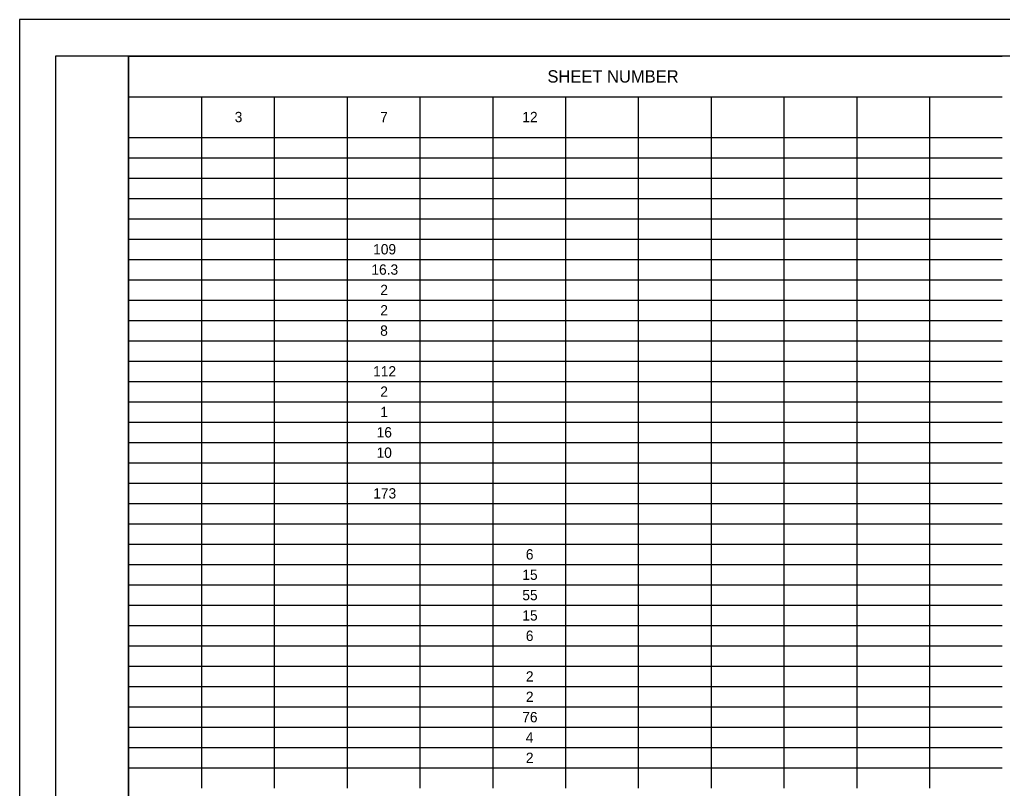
# Model space of a CAD drawing. Extents: x 0 to 34, y 0 to 22.
# Drawn here: x 0 to 13.53, y 11.42 to 22 of the extents above; entities that cross this region are included whole.
import ezdxf

# ---------------------------------------------------------------- set-up
doc = ezdxf.new("R2010")
doc.units = 0
for name, color, linetype in [('Default', 7, 'Continuous'), ('SH_Border', 7, 'Continuous'), ('SH_Cut_Line', 7, 'Continuous')]:
    doc.layers.add(name, color=color, linetype=linetype)

msp = doc.modelspace()

# ---------------------------------------------------------------- linework, layer by layer
at = {"layer": 'Default'}
for p, q in [((1.5, 21.499), (6.513, 21.499)), ((1.5, 21.499), (1.5, 21.219)), ((6.513, 21.499), (7.515, 21.499)), ((7.515, 21.499), (12.528, 21.499)), ((12.528, 21.499), (13.53, 21.499)), ((1.5, 21.219), (1.5, 20.939)), ((1.5, 20.939), (6.513, 20.939)), ((1.5, 20.939), (1.5, 20.659)), ((2.503, 20.939), (2.503, 20.659)), ((3.505, 20.939), (3.505, 20.659)), ((4.508, 20.939), (4.508, 20.659)), ((5.51, 20.939), (5.51, 20.659)), ((6.513, 20.939), (7.515, 20.939)), ((6.513, 20.939), (6.513, 20.659)), ((7.515, 20.939), (12.528, 20.939)), ((7.515, 20.939), (7.515, 20.659)), ((8.518, 20.939), (8.518, 20.659)), ((9.52, 20.939), (9.52, 20.659)), ((10.523, 20.939), (10.523, 20.659)), ((11.525, 20.939), (11.525, 20.659)), ((12.528, 20.939), (13.53, 20.939)), ((12.528, 20.939), (12.528, 20.659)), ((1.5, 20.659), (1.5, 20.379)), ((2.503, 20.659), (2.503, 20.379)), ((3.505, 20.659), (3.505, 20.379)), ((4.508, 20.659), (4.508, 20.379)), ((5.51, 20.659), (5.51, 20.379)), ((6.513, 20.659), (6.513, 20.379)), ((7.515, 20.659), (7.515, 20.379)), ((8.518, 20.659), (8.518, 20.379)), ((9.52, 20.659), (9.52, 20.379)), ((10.523, 20.659), (10.523, 20.379)), ((11.525, 20.659), (11.525, 20.379)), ((12.528, 20.659), (12.528, 20.379)), ((1.5, 20.379), (6.513, 20.379)), ((1.5, 20.379), (1.5, 20.099)), ((2.503, 20.379), (2.503, 20.099)), ((3.505, 20.379), (3.505, 20.099)), ((4.508, 20.379), (4.508, 20.099)), ((5.51, 20.379), (5.51, 20.099)), ((6.513, 20.379), (7.515, 20.379)), ((6.513, 20.379), (6.513, 20.099)), ((7.515, 20.379), (12.528, 20.379)), ((7.515, 20.379), (7.515, 20.099)), ((8.518, 20.379), (8.518, 20.099)), ((9.52, 20.379), (9.52, 20.099)), ((10.523, 20.379), (10.523, 20.099)), ((11.525, 20.379), (11.525, 20.099)), ((12.528, 20.379), (13.53, 20.379)), ((12.528, 20.379), (12.528, 20.099)), ((1.5, 20.099), (6.513, 20.099)), ((1.5, 20.099), (1.5, 18.7)), ((2.503, 20.099), (2.503, 18.7)), ((3.505, 20.099), (3.505, 18.7)), ((4.508, 20.099), (4.508, 18.7)), ((5.51, 20.099), (5.51, 18.7)), ((6.513, 20.099), (7.515, 20.099)), ((6.513, 20.099), (6.513, 18.7)), ((7.515, 20.099), (12.528, 20.099)), ((7.515, 20.099), (7.515, 18.7)), ((8.518, 20.099), (8.518, 18.7)), ((9.52, 20.099), (9.52, 18.7)), ((10.523, 20.099), (10.523, 18.7)), ((11.525, 20.099), (11.525, 18.7)), ((12.528, 20.099), (13.53, 20.099)), ((12.528, 20.099), (12.528, 18.7)), ((1.5, 19.819), (6.513, 19.819)), ((6.513, 19.819), (7.515, 19.819)), ((7.515, 19.819), (12.528, 19.819)), ((12.528, 19.819), (13.53, 19.819)), ((1.5, 19.539), (6.513, 19.539)), ((6.513, 19.539), (7.515, 19.539)), ((7.515, 19.539), (12.528, 19.539)), ((12.528, 19.539), (13.53, 19.539)), ((1.5, 19.259), (6.513, 19.259)), ((6.513, 19.259), (7.515, 19.259)), ((7.515, 19.259), (12.528, 19.259)), ((12.528, 19.259), (13.53, 19.259)), ((1.5, 18.98), (6.513, 18.98)), ((6.513, 18.98), (7.515, 18.98)), ((7.515, 18.98), (12.528, 18.98)), ((12.528, 18.98), (13.53, 18.98)), ((1.5, 18.7), (6.513, 18.7)), ((1.5, 18.7), (1.5, 18.14)), ((2.503, 18.7), (2.503, 18.14)), ((3.505, 18.7), (3.505, 18.14)), ((4.508, 18.7), (4.508, 18.14)), ((5.51, 18.7), (5.51, 18.14)), ((6.513, 18.7), (7.515, 18.7)), ((6.513, 18.7), (6.513, 18.14)), ((7.515, 18.7), (12.528, 18.7)), ((7.515, 18.7), (7.515, 18.14)), ((8.518, 18.7), (8.518, 18.14)), ((9.52, 18.7), (9.52, 18.14)), ((10.523, 18.7), (10.523, 18.14)), ((11.525, 18.7), (11.525, 18.14)), ((12.528, 18.7), (13.53, 18.7)), ((12.528, 18.7), (12.528, 18.14)), ((1.5, 18.42), (6.513, 18.42)), ((6.513, 18.42), (7.515, 18.42)), ((7.515, 18.42), (12.528, 18.42)), ((12.528, 18.42), (13.53, 18.42)), ((1.5, 18.14), (6.513, 18.14)), ((1.5, 18.14), (1.5, 17.86)), ((2.503, 18.14), (2.503, 17.86)), ((3.505, 18.14), (3.505, 17.86)), ((4.508, 18.14), (4.508, 17.86)), ((5.51, 18.14), (5.51, 17.86)), ((6.513, 18.14), (7.515, 18.14)), ((6.513, 18.14), (6.513, 17.86)), ((7.515, 18.14), (12.528, 18.14)), ((7.515, 18.14), (7.515, 17.86)), ((8.518, 18.14), (8.518, 17.86)), ((9.52, 18.14), (9.52, 17.86)), ((10.523, 18.14), (10.523, 17.86)), ((11.525, 18.14), (11.525, 17.86)), ((12.528, 18.14), (13.53, 18.14)), ((12.528, 18.14), (12.528, 17.86)), ((1.5, 17.86), (6.513, 17.86)), ((1.5, 17.86), (1.5, 17.58)), ((2.503, 17.86), (2.503, 17.58)), ((3.505, 17.86), (3.505, 17.58)), ((4.508, 17.86), (4.508, 17.58)), ((5.51, 17.86), (5.51, 17.58)), ((6.513, 17.86), (7.515, 17.86)), ((6.513, 17.86), (6.513, 17.58)), ((7.515, 17.86), (12.528, 17.86)), ((7.515, 17.86), (7.515, 17.58)), ((8.518, 17.86), (8.518, 17.58)), ((9.52, 17.86), (9.52, 17.58)), ((10.523, 17.86), (10.523, 17.58)), ((11.525, 17.86), (11.525, 17.58)), ((12.528, 17.86), (13.53, 17.86)), ((12.528, 17.86), (12.528, 17.58)), ((1.5, 17.58), (6.513, 17.58)), ((1.5, 17.58), (1.5, 17.3)), ((2.503, 17.58), (2.503, 17.3)), ((3.505, 17.58), (3.505, 17.3)), ((4.508, 17.58), (4.508, 17.3)), ((5.51, 17.58), (5.51, 17.3)), ((6.513, 17.58), (7.515, 17.58)), ((6.513, 17.58), (6.513, 17.3)), ((7.515, 17.58), (12.528, 17.58)), ((7.515, 17.58), (7.515, 17.3)), ((8.518, 17.58), (8.518, 17.3)), ((9.52, 17.58), (9.52, 17.3)), ((10.523, 17.58), (10.523, 17.3)), ((11.525, 17.58), (11.525, 17.3)), ((12.528, 17.58), (13.53, 17.58)), ((12.528, 17.58), (12.528, 17.3)), ((1.5, 17.3), (6.513, 17.3)), ((1.5, 17.3), (1.5, 17.02)), ((2.503, 17.3), (2.503, 17.02)), ((3.505, 17.3), (3.505, 17.02)), ((4.508, 17.3), (4.508, 17.02)), ((5.51, 17.3), (5.51, 17.02)), ((6.513, 17.3), (7.515, 17.3)), ((6.513, 17.3), (6.513, 17.02)), ((7.515, 17.3), (12.528, 17.3)), ((7.515, 17.3), (7.515, 17.02)), ((8.518, 17.3), (8.518, 17.02)), ((9.52, 17.3), (9.52, 17.02)), ((10.523, 17.3), (10.523, 17.02)), ((11.525, 17.3), (11.525, 17.02)), ((12.528, 17.3), (13.53, 17.3)), ((12.528, 17.3), (12.528, 17.02)), ((1.5, 17.02), (6.513, 17.02)), ((1.5, 17.02), (1.5, 16.74)), ((2.503, 17.02), (2.503, 16.74)), ((3.505, 17.02), (3.505, 16.74)), ((4.508, 17.02), (4.508, 16.74)), ((5.51, 17.02), (5.51, 16.74)), ((6.513, 17.02), (7.515, 17.02)), ((6.513, 17.02), (6.513, 16.74)), ((7.515, 17.02), (12.528, 17.02)), ((7.515, 17.02), (7.515, 16.74)), ((8.518, 17.02), (8.518, 16.74)), ((9.52, 17.02), (9.52, 16.74)), ((10.523, 17.02), (10.523, 16.74)), ((11.525, 17.02), (11.525, 16.74)), ((12.528, 17.02), (13.53, 17.02)), ((12.528, 17.02), (12.528, 16.74)), ((1.5, 16.74), (6.513, 16.74)), ((1.5, 16.74), (1.5, 16.18)), ((2.503, 16.74), (2.503, 16.18)), ((3.505, 16.74), (3.505, 16.18)), ((4.508, 16.74), (4.508, 16.18)), ((5.51, 16.74), (5.51, 16.18)), ((6.513, 16.74), (7.515, 16.74)), ((6.513, 16.74), (6.513, 16.18)), ((7.515, 16.74), (12.528, 16.74)), ((7.515, 16.74), (7.515, 16.18)), ((8.518, 16.74), (8.518, 16.18)), ((9.52, 16.74), (9.52, 16.18)), ((10.523, 16.74), (10.523, 16.18)), ((11.525, 16.74), (11.525, 16.18)), ((12.528, 16.74), (13.53, 16.74)), ((12.528, 16.74), (12.528, 16.18)), ((1.5, 16.46), (6.513, 16.46)), ((6.513, 16.46), (7.515, 16.46)), ((7.515, 16.46), (12.528, 16.46)), ((12.528, 16.46), (13.53, 16.46)), ((1.5, 16.18), (6.513, 16.18)), ((1.5, 16.18), (1.5, 15.9)), ((2.503, 16.18), (2.503, 15.9)), ((3.505, 16.18), (3.505, 15.9)), ((4.508, 16.18), (4.508, 15.9)), ((5.51, 16.18), (5.51, 15.9)), ((6.513, 16.18), (7.515, 16.18)), ((6.513, 16.18), (6.513, 15.9)), ((7.515, 16.18), (12.528, 16.18)), ((7.515, 16.18), (7.515, 15.9)), ((8.518, 16.18), (8.518, 15.9)), ((9.52, 16.18), (9.52, 15.9)), ((10.523, 16.18), (10.523, 15.9)), ((11.525, 16.18), (11.525, 15.9)), ((12.528, 16.18), (13.53, 16.18)), ((12.528, 16.18), (12.528, 15.9)), ((1.5, 15.9), (6.513, 15.9)), ((1.5, 15.9), (1.5, 15.62)), ((2.503, 15.9), (2.503, 15.62)), ((3.505, 15.9), (3.505, 15.62)), ((4.508, 15.9), (4.508, 15.62)), ((5.51, 15.9), (5.51, 15.62)), ((6.513, 15.9), (7.515, 15.9)), ((6.513, 15.9), (6.513, 15.62)), ((7.515, 15.9), (12.528, 15.9)), ((7.515, 15.9), (7.515, 15.62)), ((8.518, 15.9), (8.518, 15.62)), ((9.52, 15.9), (9.52, 15.62)), ((10.523, 15.9), (10.523, 15.62)), ((11.525, 15.9), (11.525, 15.62)), ((12.528, 15.9), (13.53, 15.9)), ((12.528, 15.9), (12.528, 15.62)), ((1.5, 15.62), (6.513, 15.62)), ((1.5, 15.62), (1.5, 15.34)), ((2.503, 15.62), (2.503, 15.34)), ((3.505, 15.62), (3.505, 15.34)), ((4.508, 15.62), (4.508, 15.34)), ((5.51, 15.62), (5.51, 15.34)), ((6.513, 15.62), (7.515, 15.62)), ((6.513, 15.62), (6.513, 15.34)), ((7.515, 15.62), (12.528, 15.62)), ((7.515, 15.62), (7.515, 15.34)), ((8.518, 15.62), (8.518, 15.34)), ((9.52, 15.62), (9.52, 15.34)), ((10.523, 15.62), (10.523, 15.34)), ((11.525, 15.62), (11.525, 15.34)), ((12.528, 15.62), (13.53, 15.62)), ((12.528, 15.62), (12.528, 15.34)), ((1.5, 15.34), (6.513, 15.34)), ((1.5, 15.34), (1.5, 14.78)), ((2.503, 15.34), (2.503, 14.78)), ((3.505, 15.34), (3.505, 14.78)), ((4.508, 15.34), (4.508, 14.78)), ((5.51, 15.34), (5.51, 14.78)), ((6.513, 15.34), (7.515, 15.34)), ((6.513, 15.34), (6.513, 14.78)), ((7.515, 15.34), (12.528, 15.34)), ((7.515, 15.34), (7.515, 14.78)), ((8.518, 15.34), (8.518, 14.78)), ((9.52, 15.34), (9.52, 14.78)), ((10.523, 15.34), (10.523, 14.78)), ((11.525, 15.34), (11.525, 14.78)), ((12.528, 15.34), (13.53, 15.34)), ((12.528, 15.34), (12.528, 14.78)), ((1.5, 15.06), (6.513, 15.06)), ((6.513, 15.06), (7.515, 15.06)), ((7.515, 15.06), (12.528, 15.06)), ((12.528, 15.06), (13.53, 15.06)), ((1.5, 14.78), (6.513, 14.78)), ((1.5, 14.78), (1.5, 14.5)), ((2.503, 14.78), (2.503, 14.5)), ((3.505, 14.78), (3.505, 14.5)), ((4.508, 14.78), (4.508, 14.5)), ((5.51, 14.78), (5.51, 14.5)), ((6.513, 14.78), (7.515, 14.78)), ((6.513, 14.78), (6.513, 14.5)), ((7.515, 14.78), (12.528, 14.78)), ((7.515, 14.78), (7.515, 14.5)), ((8.518, 14.78), (8.518, 14.5)), ((9.52, 14.78), (9.52, 14.5)), ((10.523, 14.78), (10.523, 14.5)), ((11.525, 14.78), (11.525, 14.5)), ((12.528, 14.78), (13.53, 14.78)), ((12.528, 14.78), (12.528, 14.5)), ((1.5, 14.5), (6.513, 14.5)), ((1.5, 14.5), (1.5, 14.22)), ((2.503, 14.5), (2.503, 14.22)), ((3.505, 14.5), (3.505, 14.22)), ((4.508, 14.5), (4.508, 14.22)), ((5.51, 14.5), (5.51, 14.22)), ((6.513, 14.5), (7.515, 14.5)), ((6.513, 14.5), (6.513, 14.22)), ((7.515, 14.5), (12.528, 14.5)), ((7.515, 14.5), (7.515, 14.22)), ((8.518, 14.5), (8.518, 14.22)), ((9.52, 14.5), (9.52, 14.22)), ((10.523, 14.5), (10.523, 14.22)), ((11.525, 14.5), (11.525, 14.22)), ((12.528, 14.5), (13.53, 14.5)), ((12.528, 14.5), (12.528, 14.22)), ((1.5, 14.22), (6.513, 14.22)), ((1.5, 14.22), (1.5, 13.94)), ((2.503, 14.22), (2.503, 13.94)), ((3.505, 14.22), (3.505, 13.94)), ((4.508, 14.22), (4.508, 13.94)), ((5.51, 14.22), (5.51, 13.94)), ((6.513, 14.22), (7.515, 14.22)), ((6.513, 14.22), (6.513, 13.94)), ((7.515, 14.22), (12.528, 14.22)), ((7.515, 14.22), (7.515, 13.94)), ((8.518, 14.22), (8.518, 13.94)), ((9.52, 14.22), (9.52, 13.94)), ((10.523, 14.22), (10.523, 13.94)), ((11.525, 14.22), (11.525, 13.94)), ((12.528, 14.22), (13.53, 14.22)), ((12.528, 14.22), (12.528, 13.94)), ((1.5, 13.94), (6.513, 13.94)), ((1.5, 13.94), (1.5, 11.7)), ((2.503, 13.94), (2.503, 11.7)), ((3.505, 13.94), (3.505, 11.7)), ((4.508, 13.94), (4.508, 11.7)), ((5.51, 13.94), (5.51, 11.7)), ((6.513, 13.94), (7.515, 13.94)), ((6.513, 13.94), (6.513, 11.7)), ((7.515, 13.94), (12.528, 13.94)), ((7.515, 13.94), (7.515, 11.7)), ((8.518, 13.94), (8.518, 11.7)), ((9.52, 13.94), (9.52, 11.7)), ((10.523, 13.94), (10.523, 11.7)), ((11.525, 13.94), (11.525, 11.7)), ((12.528, 13.94), (13.53, 13.94)), ((12.528, 13.94), (12.528, 11.7)), ((1.5, 13.66), (6.513, 13.66)), ((6.513, 13.66), (7.515, 13.66)), ((7.515, 13.66), (12.528, 13.66)), ((12.528, 13.66), (13.53, 13.66)), ((1.5, 13.38), (6.513, 13.38)), ((6.513, 13.38), (7.515, 13.38)), ((7.515, 13.38), (12.528, 13.38)), ((12.528, 13.38), (13.53, 13.38)), ((1.5, 13.1), (6.513, 13.1)), ((6.513, 13.1), (7.515, 13.1)), ((7.515, 13.1), (12.528, 13.1)), ((12.528, 13.1), (13.53, 13.1)), ((1.5, 12.82), (6.513, 12.82)), ((6.513, 12.82), (7.515, 12.82)), ((7.515, 12.82), (12.528, 12.82)), ((12.528, 12.82), (13.53, 12.82)), ((1.5, 12.54), (6.513, 12.54)), ((6.513, 12.54), (7.515, 12.54)), ((7.515, 12.54), (12.528, 12.54)), ((12.528, 12.54), (13.53, 12.54)), ((1.5, 12.26), (6.513, 12.26)), ((6.513, 12.26), (7.515, 12.26)), ((7.515, 12.26), (12.528, 12.26)), ((12.528, 12.26), (13.53, 12.26)), ((1.5, 11.98), (6.513, 11.98)), ((6.513, 11.98), (7.515, 11.98)), ((7.515, 11.98), (12.528, 11.98)), ((12.528, 11.98), (13.53, 11.98)), ((1.5, 11.7), (6.513, 11.7)), ((1.5, 11.7), (1.5, 11.42)), ((2.503, 11.7), (2.503, 11.42)), ((3.505, 11.7), (3.505, 11.42)), ((4.508, 11.7), (4.508, 11.42)), ((5.51, 11.7), (5.51, 11.42)), ((6.513, 11.7), (7.515, 11.7)), ((6.513, 11.7), (6.513, 11.42)), ((7.515, 11.7), (12.528, 11.7)), ((7.515, 11.7), (7.515, 11.42)), ((8.518, 11.7), (8.518, 11.42)), ((9.52, 11.7), (9.52, 11.42)), ((10.523, 11.7), (10.523, 11.42)), ((11.525, 11.7), (11.525, 11.42)), ((12.528, 11.7), (13.53, 11.7)), ((12.528, 11.7), (12.528, 11.42))]:
    msp.add_line(p, q, dxfattribs=at)
at = {"layer": 'SH_Border'}
for points in [[(0.5, 21.5), (1.5, 21.5), (1.5, 0.5), (0.5, 0.5)], [(1.5, 21.5), (33.5, 21.5), (33.5, 0.5), (1.5, 0.5)]]:
    msp.add_lwpolyline(points, close=True, dxfattribs=at)
at = {"layer": 'SH_Cut_Line'}
msp.add_lwpolyline([(0, 0), (34, 0), (34, 22), (0, 22)], close=True, dxfattribs=at)

# ---------------------------------------------------------------- texts
at = {"layer": 'Default'}
for s, height, p in [('SHEET NUMBER', 0.17, (7.267, 21.134)), ('3', 0.142, (2.961, 20.589)), ('7', 0.142, (4.964, 20.589)), ('12', 0.1417, (6.921, 20.589)), ('109', 0.1417, (4.867, 18.769)), ('16.3', 0.1417, (4.843, 18.489)), ('2', 0.142, (4.965, 18.209)), ('2', 0.142, (4.965, 17.929)), ('8', 0.142, (4.964, 17.649)), ('112', 0.1417, (4.867, 17.089)), ('2', 0.142, (4.965, 16.809)), ('1', 0.142, (4.965, 16.529)), ('16', 0.1417, (4.915, 16.249)), ('10', 0.1417, (4.914, 15.969)), ('173', 0.1417, (4.868, 15.409)), ('6', 0.142, (6.969, 14.569)), ('15', 0.1417, (6.921, 14.289)), ('55', 0.1417, (6.921, 14.009)), ('15', 0.1417, (6.921, 13.729)), ('6', 0.142, (6.969, 13.449)), ('2', 0.142, (6.97, 12.889)), ('2', 0.142, (6.97, 12.609)), ('76', 0.1417, (6.92, 12.329)), ('4', 0.142, (6.968, 12.049)), ('2', 0.142, (6.97, 11.769))]:
    msp.add_text(s, height=height, dxfattribs=at).set_placement(p)

doc.saveas('drawing.dxf')
